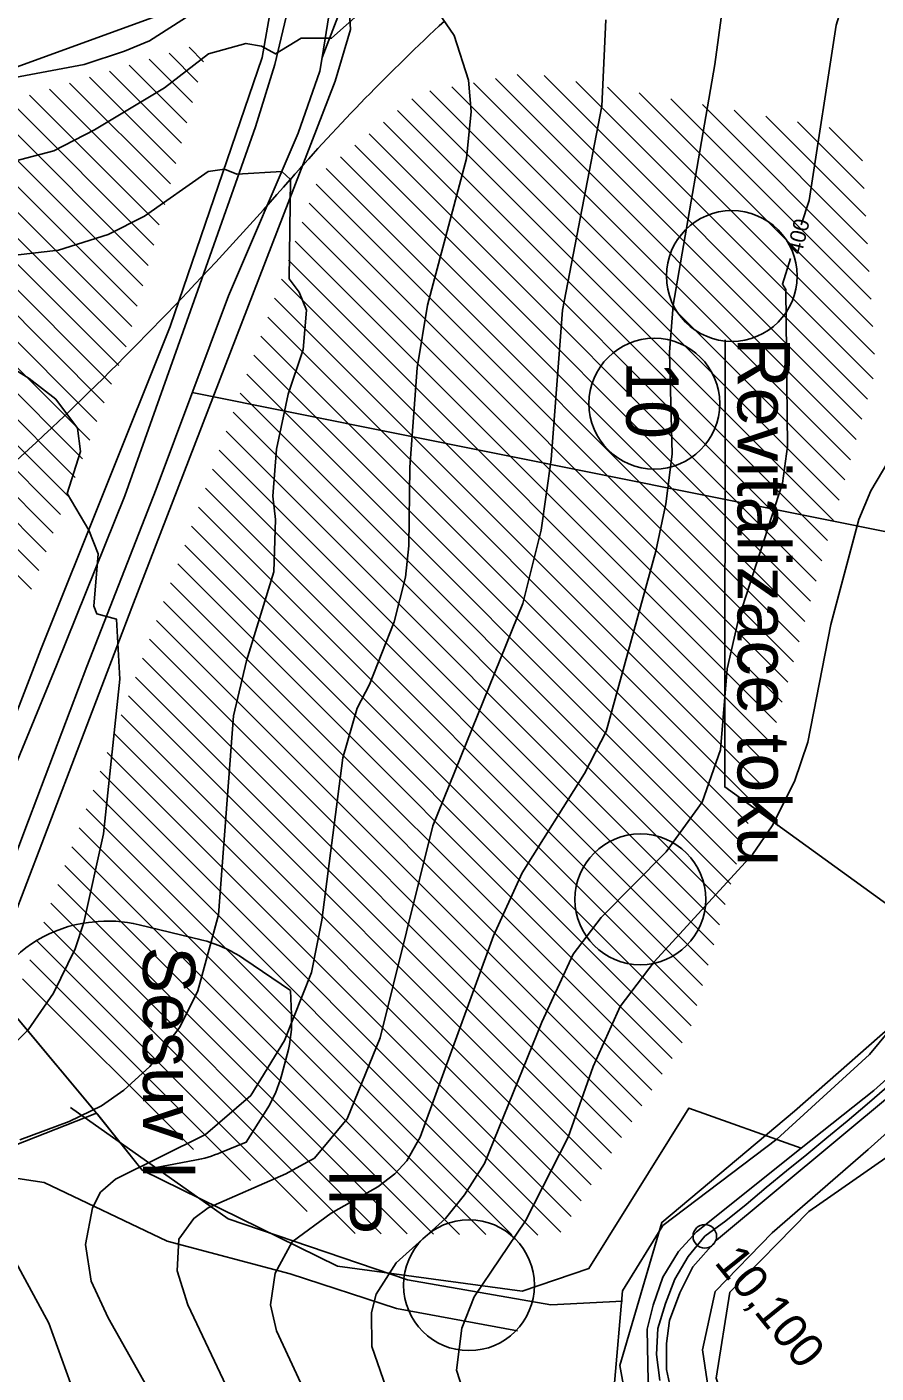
# Model space of a CAD drawing. Extents: x -510989 to -501240, y -1184665 to -1176089.
# Drawn here: x -509664 to -509340, y -1180561 to -1180047 of the extents above; entities that cross this region are included whole.
import ezdxf

# ---------------------------------------------------------------- set-up
doc = ezdxf.new("R2010")
doc.units = 0
for name, color, linetype in [('NAVRH_interakcni_prvky', 7, 'Continuous'), ('NAVRH_revitalizace_toku', 7, 'Continuous'), ('NAVRH_rozvodnice', 7, 'Continuous'), ('orna_puda', 7, 'Continuous'), ('ostatni_plocha_x_neplodna_puda', 7, 'Continuous'), ('ostatni_plocha_x_silnice', 7, 'Continuous'), ('STAV_erozne_ohrozene_plochy', 7, 'Continuous'), ('STAV_odtokove_linie', 7, 'Continuous'), ('STAV_ryhova_eroze', 7, 'Continuous'), ('STAV_systematicke_odvodneni', 7, 'Continuous'), ('STAV_vyrazne_udolnice', 7, 'Continuous'), ('trasovani_toku', 7, 'Continuous'), ('trvaly_travni_porost', 7, 'Continuous'), ('vodni_plocha_x_vodni_tok_v_koryte_umelem', 7, 'Continuous'), ('vrstevnice_01', 7, 'Continuous'), ('vrstevnice_02', 7, 'Continuous'), ('vrstevnice_04', 7, 'Continuous')]:
    doc.layers.add(name, color=color, linetype=linetype)

msp = doc.modelspace()

# ---------------------------------------------------------------- linework, layer by layer
at = {"layer": 'NAVRH_interakcni_prvky'}
msp.add_lwpolyline([(-509647.6, -1180459.69), (-509587.32, -1180502.16), (-509518.82, -1180525.45), (-509464.02, -1180535.04), (-509436.62, -1180533.67)], dxfattribs=at)
at = {"layer": 'NAVRH_revitalizace_toku'}
for points in [[(-509251.68, -1180051.44), (-509284.55, -1180226.79), (-509300.99, -1180374.75), (-509325.65, -1180421.33), (-509370.86, -1180461.06), (-509421.55, -1180503.53), (-509437.68, -1180558.22), (-509431.14, -1180593.95), (-509419.28, -1180621.11), (-509382.45, -1180650.58), (-509372.86, -1180654.24)], [(-509217.43, -1180056.92), (-509232.5, -1180170.63), (-509254.42, -1180314.47), (-509261.27, -1180377.49), (-509279.08, -1180419.96), (-509306.48, -1180458.32), (-509365.38, -1180499.42), (-509395.55, -1180530.26), (-509400.81, -1180563.08), (-509388.25, -1180600.36), (-509365.16, -1180623.45), (-509328.69, -1180628.72), (-509284.94, -1180642.09), (-509256.17, -1180678.15), (-509235.24, -1180752.86), (-509207.84, -1180777.52)], [(-509313.32, -1180398.04), (-509397.52, -1180337.11), (-509397.42, -1180166.22)]]:
    msp.add_lwpolyline(points, dxfattribs=at)
at = {"layer": 'NAVRH_rozvodnice'}
for centre, radius, start, end in [((-508952.13, -1180641.28), 813.32, 132.79738, 138.74782), ((-510663.94, -1179139.95), 1463.58, 313.9021, 318.74782), ((-510184.35, -1179638.28), 771.96, 309.14233, 313.9021)]:
    msp.add_arc(centre, radius, start, end, dxfattribs=at)
at = {"layer": 'orna_puda'}
for points in [[(-509925.07, -1180133.29), (-509890.12, -1180122.4), (-509861.83, -1180113.58), (-509816.6, -1180104.43), (-509754.45, -1180090.32), (-509722.44, -1180081.65), (-509563.62, -1180023.92)], [(-509562.83, -1180032.49), (-509569.47, -1180061.07), (-509576.88, -1180084.83), (-509599.01, -1180147.29), (-509626.86, -1180225.88), (-509653.04, -1180290.71), (-509675.52, -1180345.29), (-509689.08, -1180382.89), (-509699.18, -1180394.47), (-509708.09, -1180406.34), (-509714.44, -1180419.43), (-509727.66, -1180454.24), (-509725.13, -1180482.57), (-509730.24, -1180497.75), (-509739.42, -1180520), (-509812.99, -1180541.95), (-509867.93, -1180557.38), (-509878.28, -1180550.47), (-509893.97, -1180543.48), (-509932.82, -1180548.16)], [(-509325.64, -1180439.73), (-509340.55, -1180453.11), (-509368.25, -1180475.22), (-509411.24, -1180459.85), (-509449.45, -1180521.23), (-509475.01, -1180529.87), (-509545.52, -1180520.3), (-509620.2, -1180483.63), (-509637.72, -1180461.75), (-509684.7, -1180405.65), (-509663.64, -1180349.99), (-509641.36, -1180291.15), (-509614.94, -1180223.33), (-509587.22, -1180149.46), (-509560.59, -1180087.35), (-509552.27, -1180063.61), (-509551.44, -1180058.44), (-509541.37, -1180032.19)]]:
    msp.add_lwpolyline(points, dxfattribs=at)
at = {"layer": 'ostatni_plocha_x_neplodna_puda'}
for points in [[(-509547.11, -1180025.3), (-509535.5, -1180019.37), (-509541.37, -1180032.19), (-509551.44, -1180058.44), (-509546.79, -1180029.63)], [(-509687.34, -1180412.63), (-509684.7, -1180405.65), (-509637.72, -1180461.75), (-509708.44, -1180489.55), (-509701.45, -1180480.97), (-509692.29, -1180443.92)]]:
    msp.add_lwpolyline(points, close=True, dxfattribs=at)
at = {"layer": 'ostatni_plocha_x_silnice'}
for points in [[(-509546.79, -1180029.63), (-509551.44, -1180058.44), (-509552.27, -1180063.61), (-509560.59, -1180087.35), (-509587.22, -1180149.46), (-509614.94, -1180223.33), (-509641.36, -1180291.15), (-509663.64, -1180349.99), (-509684.7, -1180405.65), (-509687.34, -1180412.63), (-509692.29, -1180443.92), (-509701.45, -1180480.97), (-509708.44, -1180489.55), (-509717.69, -1180500.89), (-509719.09, -1180504.59), (-509721.42, -1180510.79), (-509730.35, -1180537.79), (-509736.42, -1180553.04), (-509753.97, -1180597.17)], [(-509769.58, -1180593.16), (-509739.42, -1180520), (-509730.24, -1180497.75), (-509725.13, -1180482.57), (-509723.12, -1180476.62), (-509715.98, -1180446.18), (-509699.09, -1180410.64), (-509694.62, -1180398.26), (-509689.08, -1180382.89), (-509675.52, -1180345.29), (-509653.04, -1180290.71), (-509626.86, -1180225.88), (-509599.01, -1180147.29), (-509576.88, -1180084.83), (-509569.47, -1180061.07), (-509562.83, -1180032.49)]]:
    msp.add_lwpolyline(points, dxfattribs=at)
at = {"layer": 'STAV_erozne_ohrozene_plochy'}
for p, q in [((-509602.31, -1180054.49), (-509596.8, -1180060)), ((-509617.55, -1180059.05), (-509601.02, -1180075.57)), ((-509609.93, -1180056.77), (-509598.91, -1180067.79)), ((-509632.79, -1180063.61), (-509605.24, -1180091.15)), ((-509625.17, -1180061.33), (-509603.13, -1180083.36)), ((-509476.87, -1180064.92), (-509345.13, -1180196.65)), ((-509466.58, -1180065.3), (-509342.96, -1180188.93)), ((-509655.65, -1180070.44), (-509611.58, -1180114.51)), ((-509648.03, -1180068.16), (-509609.47, -1180106.72)), ((-509640.41, -1180065.89), (-509607.36, -1180098.94)), ((-509501.9, -1180069.58), (-509351.66, -1180219.83)), ((-509493.56, -1180068.03), (-509349.48, -1180212.1)), ((-509485.21, -1180066.47), (-509347.31, -1180204.38)), ((-509454.48, -1180067.51), (-509340.78, -1180181.2)), ((-509442.37, -1180069.71), (-509340.29, -1180171.8)), ((-509670.89, -1180075), (-509615.8, -1180130.09)), ((-509663.27, -1180072.72), (-509613.69, -1180122.3)), ((-509517.12, -1180074.17), (-509356, -1180235.28)), ((-509510.25, -1180071.14), (-509353.83, -1180227.55)), ((-509430.27, -1180071.92), (-509340.94, -1180161.24)), ((-509418.16, -1180074.13), (-509341.6, -1180150.69)), ((-509686.13, -1180079.56), (-509620.03, -1180145.66)), ((-509678.51, -1180077.28), (-509617.92, -1180137.87)), ((-509522.57, -1180078.61), (-509358.18, -1180243)), ((-509406.05, -1180076.33), (-509342.25, -1180140.13)), ((-509393.95, -1180078.54), (-509342.91, -1180129.58)), ((-509381.84, -1180080.74), (-509343.56, -1180119.03)), ((-509701.37, -1180084.12), (-509624.25, -1180161.24)), ((-509693.75, -1180081.84), (-509622.14, -1180153.45)), ((-509528.03, -1180083.05), (-509360.35, -1180250.73)), ((-509369.74, -1180082.95), (-509344.22, -1180108.47)), ((-509357.63, -1180085.16), (-509344.87, -1180097.92)), ((-509724.23, -1180090.95), (-509631.94, -1180183.25)), ((-509716.61, -1180088.68), (-509629.16, -1180176.13)), ((-509708.99, -1180086.4), (-509626.37, -1180169.01)), ((-509533.48, -1180087.5), (-509362.53, -1180258.45)), ((-509739.47, -1180095.51), (-509637.51, -1180197.48)), ((-509731.85, -1180093.23), (-509634.72, -1180190.36)), ((-509544.39, -1180096.38), (-509366.88, -1180273.9)), ((-509538.94, -1180091.94), (-509364.7, -1180266.18)), ((-509754.71, -1180100.07), (-509643.07, -1180211.71)), ((-509747.09, -1180097.79), (-509640.29, -1180204.6)), ((-509549.85, -1180100.83), (-509369.05, -1180281.63)), ((-509769.96, -1180104.63), (-509648.64, -1180225.94)), ((-509762.33, -1180102.35), (-509645.86, -1180218.83)), ((-509553.76, -1180106.82), (-509371.22, -1180289.35)), ((-509792.82, -1180111.47), (-509656.99, -1180247.29)), ((-509785.2, -1180109.19), (-509654.21, -1180240.18)), ((-509777.58, -1180106.91), (-509651.42, -1180233.06)), ((-509808.06, -1180116.02), (-509662.56, -1180261.53)), ((-509800.44, -1180113.75), (-509659.77, -1180254.41)), ((-509556.4, -1180114.07), (-509373.4, -1180297.08)), ((-509559.05, -1180121.33), (-509375.57, -1180304.8)), ((-509561.69, -1180128.59), (-509377.75, -1180312.53)), ((-509564.33, -1180135.84), (-509379.92, -1180320.25)), ((-509566.98, -1180143.1), (-509382.1, -1180327.98)), ((-509569.62, -1180150.36), (-509384.27, -1180335.7)), ((-509572.26, -1180157.61), (-509386.44, -1180343.43)), ((-509574.9, -1180164.87), (-509388.62, -1180351.15)), ((-509577.55, -1180172.13), (-509390.79, -1180358.88)), ((-509580.19, -1180179.38), (-509392.97, -1180366.61)), ((-509582.83, -1180186.64), (-509395.14, -1180374.33)), ((-509585.48, -1180193.89), (-509397.32, -1180382.06)), ((-509588.12, -1180201.15), (-509399.49, -1180389.78)), ((-509590.76, -1180208.41), (-509401.66, -1180397.51)), ((-509593.41, -1180215.66), (-509403.84, -1180405.23)), ((-509596.05, -1180222.92), (-509406.01, -1180412.96)), ((-509598.69, -1180230.18), (-509408.19, -1180420.68)), ((-509601.34, -1180237.43), (-509410.36, -1180428.41)), ((-509603.98, -1180244.69), (-509413.78, -1180434.89)), ((-509606.65, -1180251.92), (-509417.64, -1180440.93)), ((-509609.35, -1180259.12), (-509421.5, -1180446.96)), ((-509612.04, -1180266.32), (-509425.37, -1180453)), ((-509614.74, -1180273.53), (-509429.23, -1180459.04)), ((-509617.43, -1180280.73), (-509433.09, -1180465.07)), ((-509620.13, -1180287.94), (-509436.96, -1180471.11)), ((-509622.82, -1180295.14), (-509440.82, -1180477.15)), ((-509625.52, -1180302.35), (-509444.68, -1180483.18)), ((-509628.21, -1180309.55), (-509448.54, -1180489.22)), ((-509630.91, -1180316.75), (-509452.41, -1180495.26)), ((-509633.6, -1180323.96), (-509456.27, -1180501.29)), ((-509636.3, -1180331.16), (-509460.13, -1180507.33)), ((-509638.99, -1180338.37), (-509468.94, -1180508.42)), ((-509641.69, -1180345.57), (-509478.93, -1180508.33)), ((-509644.38, -1180352.78), (-509488.92, -1180508.24)), ((-509647.08, -1180359.98), (-509498.9, -1180508.16)), ((-509649.78, -1180367.18), (-509508.89, -1180508.07)), ((-509652.47, -1180374.39), (-509518.88, -1180507.98)), ((-509655.17, -1180381.59), (-509528.86, -1180507.9)), ((-509657.86, -1180388.8), (-509538.85, -1180507.81)), ((-509640.73, -1180388.95), (-509639.34, -1180388.78)), ((-509621.43, -1180389.81), (-509597.75, -1180395.56)), ((-509660.56, -1180396), (-509557.16, -1180499.4)), ((-509663.25, -1180403.21), (-509578.88, -1180487.57)), ((-509665.95, -1180410.41), (-509600.61, -1180475.74)), ((-509564.79, -1180439.39), (-509566.84, -1180447.03))]:
    msp.add_line(p, q, dxfattribs=at)
for points in [[(-509581.36, -1180402.84), (-509563.58, -1180414.98), (-509563.14, -1180424.06)], [(-509638.07, -1180461.33), (-509678.1, -1180413.53), (-509675.6, -1180409.95)], [(-509572.84, -1180460.76), (-509580.46, -1180472.83), (-509590.11, -1180476.85)], [(-509600.05, -1180479.83), (-509620.2, -1180483.63), (-509637.38, -1180462.18)]]:
    msp.add_lwpolyline(points, dxfattribs=at)
for centre, start, end in [((-509634.61, -1180438.57), 97.035, 145.081), ((-509633.22, -1180438.4), 76.3626, 97.035), ((-509609.54, -1180444.15), 55.6961, 76.3626), ((-509613.09, -1180426.44), 344.9989, 2.7275), ((-509615.13, -1180434.09), 327.7604, 344.9989), ((-509676.41, -1180493.43), 38.6853, 39.9439), ((-509609.33, -1180430.69), 280.6925, 292.6113)]:
    msp.add_arc(centre, 50, start, end, dxfattribs=at)
at = {"layer": 'STAV_odtokove_linie'}
msp.add_line((-509601.08, -1180186.4), (-509274.3, -1180251.98), dxfattribs=at)
msp.add_circle((-509424.44, -1180190.65), 25, dxfattribs=at)
at = {"layer": 'STAV_ryhova_eroze'}
for centre in [(-509394.82, -1180141.88), (-509429.79, -1180380.11), (-509495.3, -1180527.55)]:
    msp.add_circle(centre, 25, dxfattribs=at)
at = {"layer": 'STAV_systematicke_odvodneni'}
for p, q in [((-509543.84, -1179986), (-509540.65, -1180047.74)), ((-509574.42, -1180058.44), (-509570.17, -1180034.49)), ((-509540.65, -1180047.74), (-509546.5, -1180067.43)), ((-509609.53, -1180161.16), (-509574.42, -1180058.44)), ((-509546.5, -1180067.43), (-509624.17, -1180268.6)), ((-509659.01, -1180284.63), (-509609.53, -1180161.16)), ((-509624.17, -1180268.6), (-509676.84, -1180406.44)), ((-509748.11, -1180515.48), (-509659.01, -1180284.63)), ((-509342.22, -1180439.44), (-509312.43, -1180403.25)), ((-509377.61, -1180471.69), (-509342.22, -1180439.44)), ((-509313.47, -1180449.56), (-509342.73, -1180475.64)), ((-509421.23, -1180504.68), (-509377.61, -1180471.69)), ((-509342.73, -1180475.64), (-509379.43, -1180507.58)), ((-509436.66, -1180529.7), (-509421.23, -1180504.68)), ((-509379.43, -1180507.58), (-509401.24, -1180529.93)), ((-509439.85, -1180566.42), (-509436.66, -1180529.7)), ((-509401.24, -1180529.93), (-509406.03, -1180552.28)), ((-509406.03, -1180552.28), (-509402.31, -1180576.76))]:
    msp.add_line(p, q, dxfattribs=at)
at = {"layer": 'STAV_vyrazne_udolnice'}
msp.add_lwpolyline([(-509476.81, -1180544.93), (-509523.03, -1180536.49), (-509563.62, -1180523.23), (-509610.64, -1180510.78), (-509657.67, -1180488.28), (-509682.18, -1180484.66)], dxfattribs=at)
at = {"layer": 'trasovani_toku'}
for p, q in [((-509343.1, -1180458.39), (-509335.55, -1180451.84)), ((-509350.69, -1180464.9), (-509343.1, -1180458.39)), ((-509358.48, -1180471.18), (-509350.69, -1180464.9)), ((-509366.09, -1180477.66), (-509358.48, -1180471.18)), ((-509373.89, -1180483.91), (-509366.09, -1180477.66)), ((-509381.68, -1180490.19), (-509373.89, -1180483.91)), ((-509389.29, -1180496.68), (-509381.68, -1180490.19)), ((-509397.12, -1180502.9), (-509389.29, -1180496.68)), ((-509405.14, -1180508.87), (-509397.12, -1180502.9)), ((-509411.48, -1180516.61), (-509405.14, -1180508.87)), ((-509416.61, -1180525.19), (-509411.48, -1180516.61)), ((-509420.13, -1180534.55), (-509416.61, -1180525.19)), ((-509423.11, -1180544.09), (-509420.13, -1180534.55)), ((-509423.61, -1180554.08), (-509423.11, -1180544.09)), ((-509422.31, -1180564), (-509423.61, -1180554.08))]:
    msp.add_line(p, q, dxfattribs=at)
msp.add_circle((-509405.14, -1180508.87), 4.5, dxfattribs=at)
at = {"layer": 'trvaly_travni_porost'}
for points in [[(-509967.35, -1180059.23), (-509800.89, -1180057.29), (-509791.69, -1180055.81), (-509786.94, -1180054.7), (-509694.28, -1180014.14), (-509603.1, -1179974.24), (-509580.47, -1179962.08), (-509571.85, -1179922.59), (-509567.68, -1179922.21), (-509565.24, -1180006.24), (-509563.62, -1180023.92), (-509722.44, -1180081.65), (-509754.45, -1180090.32), (-509816.6, -1180104.43), (-509819.08, -1180096.5), (-509827.86, -1180088.44), (-509830.07, -1180080.34), (-509842.17, -1180079.77), (-509878.93, -1180085.53), (-509891.98, -1180088.58), (-509953.4, -1180109.7)], [(-509326.27, -1180644.8), (-509346.73, -1180642.81), (-509360.72, -1180641.45), (-509368.64, -1180639.14), (-509378.51, -1180635.37), (-509384.95, -1180630.75), (-509392.49, -1180622.45), (-509398.69, -1180612.85), (-509414.82, -1180578.01), (-509417.86, -1180568.68), (-509419.77, -1180559.8), (-509419.77, -1180549.77), (-509418.65, -1180541.09), (-509414.72, -1180530.49), (-509409.69, -1180520.55), (-509400.71, -1180510.32), (-509332.19, -1180453.34)], [(-509719.49, -1180567.82), (-509715.84, -1180557.88), (-509714.27, -1180531.29), (-509719.09, -1180504.59), (-509717.69, -1180500.89), (-509708.44, -1180489.55), (-509637.72, -1180461.75), (-509620.2, -1180483.63), (-509545.52, -1180520.3), (-509475.01, -1180529.87), (-509449.45, -1180521.23), (-509411.24, -1180459.85), (-509368.25, -1180475.22), (-509408.3, -1180507.2), (-509415.15, -1180514.71), (-509421.2, -1180524.49), (-509424.91, -1180535.2), (-509427.22, -1180544.4), (-509426.83, -1180564.36)]]:
    msp.add_lwpolyline(points, dxfattribs=at)
at = {"layer": 'vodni_plocha_x_vodni_tok_v_koryte_umelem'}
for points in [[(-509330.29, -1180650.97), (-509340.3, -1180650.85), (-509345.91, -1180650.45), (-509352.23, -1180649.99), (-509361.45, -1180649.33), (-509370.12, -1180647.38), (-509377.83, -1180643.94), (-509389.49, -1180637.49), (-509394.46, -1180632.28), (-509402.02, -1180622.88), (-509420.81, -1180585.39), (-509426.83, -1180564.36), (-509427.22, -1180544.4), (-509424.91, -1180535.2), (-509421.2, -1180524.49), (-509415.15, -1180514.71), (-509408.3, -1180507.2), (-509368.25, -1180475.22), (-509340.55, -1180453.11), (-509325.64, -1180439.73)], [(-509332.19, -1180453.34), (-509400.71, -1180510.32), (-509409.69, -1180520.55), (-509414.72, -1180530.49), (-509418.65, -1180541.09), (-509419.77, -1180549.77), (-509419.77, -1180559.8), (-509417.86, -1180568.68), (-509414.82, -1180578.01), (-509398.69, -1180612.85), (-509392.49, -1180622.45), (-509384.95, -1180630.75), (-509378.51, -1180635.37), (-509368.64, -1180639.14), (-509360.72, -1180641.45), (-509346.73, -1180642.81), (-509326.27, -1180644.8)]]:
    msp.add_lwpolyline(points, dxfattribs=at)
at = {"layer": 'vrstevnice_01'}
for points in [[(-509377.31, -1179961), (-509362.59, -1179964), (-509347.31, -1179965), (-509344, -1179977), (-509342.5, -1179989), (-509343.59, -1180003), (-509346.69, -1180019), (-509354.91, -1180046), (-509365.31, -1180113), (-509368.27, -1180122.3)], [(-509704.91, -1180074), (-509702.19, -1180076), (-509697, -1180075), (-509668.91, -1180066), (-509642.41, -1180061), (-509627, -1180056), (-509617.5, -1180052), (-509589.59, -1180034)], [(-509443, -1180044), (-509444.5, -1180077), (-509459.59, -1180155), (-509463.91, -1180212), (-509467.69, -1180239), (-509474.69, -1180267), (-509509.09, -1180352), (-509529.31, -1180433), (-509541.91, -1180464), (-509554.41, -1180479), (-509565.31, -1180485), (-509595, -1180498), (-509600.5, -1180502), (-509606.19, -1180510), (-509606.91, -1180522), (-509602.81, -1180535), (-509588.09, -1180566)], [(-509923.91, -1180087), (-509890.31, -1180092), (-509820.69, -1180097), (-509784.81, -1180105), (-509733.69, -1180127), (-509711, -1180133), (-509677.59, -1180135), (-509652.19, -1180132), (-509633.19, -1180126), (-509619.41, -1180119), (-509595, -1180102)], [(-509595, -1180102), (-509588.81, -1180101), (-509584.09, -1180103), (-509566.81, -1180102), (-509563.59, -1180105), (-509564.09, -1180143), (-509560.19, -1180148), (-509557.41, -1180155), (-509558.69, -1180170), (-509564.41, -1180187), (-509568.91, -1180208), (-509570.31, -1180226), (-509569.31, -1180235), (-509569.91, -1180255), (-509580.31, -1180289), (-509585.31, -1180310), (-509591, -1180386), (-509599, -1180415), (-509605.81, -1180429), (-509617.31, -1180444), (-509627.19, -1180453), (-509635.81, -1180459), (-509648.19, -1180465), (-509667, -1180472)], [(-509372.36, -1180135.14), (-509375.5, -1180145), (-509374.19, -1180147), (-509373.59, -1180207), (-509375.5, -1180221), (-509392.31, -1180273), (-509396.59, -1180292), (-509399.09, -1180323), (-509406.19, -1180343), (-509419.91, -1180362), (-509444.81, -1180387), (-509455.5, -1180401), (-509467.5, -1180427), (-509489.31, -1180481), (-509497, -1180493), (-509504.31, -1180502), (-509523.19, -1180519), (-509530.81, -1180531), (-509532.59, -1180538), (-509532.41, -1180551), (-509524.81, -1180573)], [(-509677.69, -1180502), (-509655.91, -1180542), (-509647.59, -1180565)]]:
    msp.add_lwpolyline(points, dxfattribs=at)
at = {"layer": 'vrstevnice_02'}
for points in [[(-509554.5, -1180576), (-509568.91, -1180545), (-509571.19, -1180535), (-509569.41, -1180523), (-509562.91, -1180511), (-509548, -1180500), (-509530.19, -1180490), (-509523.69, -1180485), (-509519, -1180480), (-509513.91, -1180471), (-509485.91, -1180394), (-509474.91, -1180370), (-509451.19, -1180332), (-509442.91, -1180316), (-509423.81, -1180247), (-509420, -1180229), (-509417.59, -1180210), (-509418.69, -1180171), (-509417.19, -1180153), (-509401.31, -1180061), (-509397.09, -1180030)], [(-509529.91, -1180035), (-509547.81, -1180051), (-509559.41, -1180051), (-509569.31, -1180057), (-509574.59, -1180054), (-509580.59, -1180053), (-509594.91, -1180057), (-509611.69, -1180070), (-509638.41, -1180086), (-509654, -1180094), (-509677, -1180100), (-509695.69, -1180101), (-509716.31, -1180098), (-509745, -1180090), (-509780.41, -1180076), (-509795.5, -1180074), (-509810.59, -1180073)], [(-509616.91, -1180569), (-509633.19, -1180540), (-509639.69, -1180526), (-509641.91, -1180512), (-509639.19, -1180498), (-509636.19, -1180492), (-509630.41, -1180487), (-509596.09, -1180470), (-509578.69, -1180455), (-509565.81, -1180434), (-509555.5, -1180408), (-509551.59, -1180388), (-509543.59, -1180326), (-509538.09, -1180307), (-509533.31, -1180298), (-509523.91, -1180274), (-509519.59, -1180257), (-509518.31, -1180245), (-509517.91, -1180215), (-509515.09, -1180177), (-509511.19, -1180153), (-509496.19, -1180097), (-509494.41, -1180079), (-509495.5, -1180067), (-509500.91, -1180050), (-509508.5, -1180039)], [(-509673.31, -1180175), (-509663.41, -1180181), (-509653.19, -1180189), (-509644.91, -1180200), (-509643.81, -1180209), (-509648.91, -1180225), (-509640.69, -1180239), (-509637.09, -1180248), (-509638.69, -1180268), (-509637.59, -1180271), (-509630.09, -1180273), (-509628.81, -1180296), (-509635, -1180355), (-509642.5, -1180389), (-509645.81, -1180399), (-509654.19, -1180416), (-509663.81, -1180430), (-509685.69, -1180452)], [(-509326.19, -1180198), (-509341.69, -1180224), (-509346.31, -1180235), (-509356.91, -1180275), (-509365.81, -1180320), (-509370.91, -1180335), (-509379.41, -1180352), (-509386.91, -1180363), (-509424.5, -1180404), (-509437.5, -1180421), (-509447.81, -1180444), (-509457.41, -1180471), (-509473.69, -1180503), (-509493.31, -1180532), (-509498.09, -1180544), (-509500.09, -1180560), (-509493.91, -1180579)]]:
    msp.add_lwpolyline(points, dxfattribs=at)

# ---------------------------------------------------------------- texts
at = {"layer": 'NAVRH_interakcni_prvky'}
msp.add_text('IP', height=20, rotation=270, dxfattribs=at).set_placement((-509548.71, -1180482.99))
at = {"layer": 'NAVRH_revitalizace_toku'}
msp.add_text('Revitalizace toku', height=20, rotation=270, dxfattribs=at).set_placement((-509392.63, -1180165.23))
at = {"layer": 'STAV_erozne_ohrozene_plochy'}
msp.add_text('Sesuv I', height=20, rotation=270, dxfattribs=at).set_placement((-509619.95, -1180398.06))
at = {"layer": 'STAV_odtokove_linie'}
msp.add_text('10', height=20, rotation=270, dxfattribs=at).set_placement((-509435.16, -1180174.43))
at = {"layer": 'trasovani_toku'}
msp.add_text('10,100', height=13, rotation=308.8727, dxfattribs=at).set_placement((-509401.81, -1180518.94))
at = {"layer": 'vrstevnice_04'}
msp.add_text('400', height=6, rotation=76.1915, dxfattribs=at).set_placement((-509368.15, -1180133.94))

doc.saveas('drawing.dxf')
